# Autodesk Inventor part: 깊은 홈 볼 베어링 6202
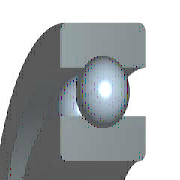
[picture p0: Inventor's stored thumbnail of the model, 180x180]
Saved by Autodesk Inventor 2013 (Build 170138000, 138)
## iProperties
IsCustomPart: 1
Created: 2012-02
Part Number: 깊은 홈 볼 베어링 6202
Material: 강철, 연강
Description: 깊은 그루부 볼 베어링
Document SubType Name: Modeling
Standard: JIS B 1521
Designer: mdu-01
Standards Organization: JIS
Language: ko-KR
Size Designation: 6202 15x35x11
Categories: <MemberInstance><Categories><Category DisplayName="샤프트 부품" InternalName="7f7aeb1f-a693-4053-b835-cee3144e0d98" Mnemonic="SHFT"><Category DisplayName="베어링" Inter
Density: 1 g/cm^3
Author: mdu-01
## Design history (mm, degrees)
sketch "스케치" dims "d0" = 5.2 (= -0.26 x WD + 0.26 x BD)
  geometry: L1 (2.9, 12.5)-(8.1, 12.5); L2 (5.5, 12.5)-(5.5, 9.9); L3 (5.5, 12.5)-(5.5, 15.1); L4 (3.568, 10.76)-(0, 10.76); L5 (0, 7.5)-(11, 7.5); L6 (3.568, 14.24)-(0, 14.24); L7 (0, 17.5)-(11, 17.5); L8 (11, 7.5)-(11, 10.76); L9 (7.432, 10.76)-(11, 10.76); L10 (7.432, 14.24)-(11, 14.24); L11 (11, 17.5)-(11, 14.24); L12 (-1.4, 0)-(8.4, 0) reference; L13 (0, -0.3)-(0, 5.3) reference
  constraints: 22 end point, 4 point on line, 2 collinear, 2 perpendicular, 2 symmetric about line, 1 midpoint, 1 parallel, 14 other
  dimensions: "d9" = 15 diameter of L5 L12 (= WD); "d11" = 35 diameter of L7 L12 (= BD); "d12" = 11 distance between parallel lines of L8 L13 (= KB); "d13" = 21.52 diameter of L9 L12 (= 0.326 x BD + 0.674 x WD)
revolve "본체" stored, may be unused: angle "d6" = 90 deg
revolve "볼" stored, may be unused: angle "d7" = 90 deg
pattern_circular "IDS_ARRAYBALL[SIMPL:T]" dims angle "d3" = 360 deg
body "Solid1"
fillet "모깎기1" dims "d1" = 0.6 (= KRS)
other parameters: "WD" = 15 [user parameter; used in 5 equation terms], "BD" = 35 [user parameter; used in 5 equation terms], "KB" = 11 [user parameter; used in 1 equation term], "KRS" = 0.6 [user parameter; used in 1 equation term], "d4" = 0, "d5" = 0, "d8" = 0, "d14" = 0, "d15" = 0, "BBA" = 0 [user parameter], "BC0" = 3750000 [user parameter], "BC" = 7800000 [user parameter], "BR" = 17.5 (= 0.5 x BD) [user parameter], "WR" = 7.5 (= 0.5 x WD) [user parameter]
